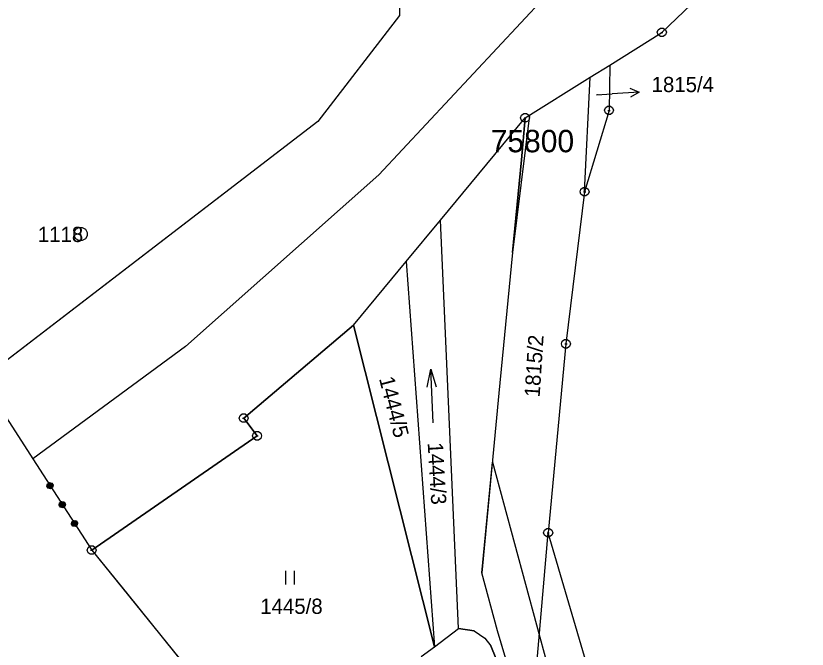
# Model space of a CAD drawing. Extents: x -779618 to -776429, y -1144546 to -1143350.
# Drawn here: x -779325.9 to -779237.8, y -1144354.3 to -1144283.6 of the extents above; entities that cross this region are included whole.
import ezdxf

# ---------------------------------------------------------------- set-up
doc = ezdxf.new("R2010")
doc.units = 0
for name, color, linetype in [('1', 7, 'Continuous'), ('11', 7, 'Continuous'), ('2', 7, 'Continuous'), ('3', 7, 'Continuous'), ('6', 7, 'Continuous'), ('7', 7, 'Continuous'), ('8', 7, 'Continuous')]:
    doc.layers.add(name, color=color, linetype=linetype)

msp = doc.modelspace()

# ---------------------------------------------------------------- linework, layer by layer
at = {"layer": '1'}
for p, q in [((-779253.95, -1144285.5), (-779237.76, -1144269.92)), ((-779283.19, -1144283.63), (-779292.3, -1144295.43)), ((-779259.77, -1144289.14), (-779253.95, -1144285.5)), ((-779261.95, -1144290.5), (-779259.77, -1144289.14)), ((-779259.77, -1144289.14), (-779259.84, -1144294.2)), ((-779269.19, -1144295.03), (-779261.95, -1144290.5)), ((-779262.56, -1144303.28), (-779261.95, -1144290.5)), ((-779259.84, -1144294.2), (-779262.56, -1144303.28)), ((-779292.3, -1144295.43), (-779329.76, -1144324.23)), ((-779278.62, -1144306.44), (-779269.19, -1144295.03)), ((-779269.19, -1144295.03), (-779269.59, -1144299.72)), ((-779269.59, -1144299.72), (-779272.11, -1144325.73)), ((-779262.56, -1144303.28), (-779264.64, -1144320.25)), ((-779282.44, -1144311.07), (-779278.62, -1144306.44)), ((-779276.6, -1144352), (-779278.62, -1144306.44)), ((-779288.3, -1144318.16), (-779282.44, -1144311.07)), ((-779282.44, -1144311.07), (-779279.28, -1144354.03)), ((-779288.3, -1144318.16), (-779300.55, -1144328.53)), ((-779279.28, -1144354.03), (-779288.3, -1144318.16)), ((-779264.64, -1144320.25), (-779266.62, -1144341.31)), ((-779329.76, -1144324.23), (-779324.06, -1144333.07)), ((-779272.11, -1144325.73), (-779274.02, -1144345.79)), ((-779300.55, -1144328.53), (-779299.06, -1144330.51)), ((-779299.06, -1144330.51), (-779317.49, -1144343.25)), ((-779324.06, -1144333.07), (-779317.49, -1144343.25)), ((-779267.93, -1144356.45), (-779266.62, -1144341.31)), ((-779261.4, -1144359.15), (-779266.62, -1144341.31)), ((-779317.49, -1144343.25), (-779313.48, -1144348.21)), ((-779272.28, -1144352.24), (-779274.02, -1144345.79)), ((-779313.48, -1144348.21), (-779297.37, -1144368.14)), ((-779279.28, -1144354.03), (-779276.6, -1144352)), ((-779274.88, -1144352.25), (-779276.6, -1144352)), ((-779274.88, -1144352.25), (-779273.67, -1144353.06)), ((-779273.67, -1144353.06), (-779273.01, -1144353.91)), ((-779268.45, -1144365.11), (-779272.28, -1144352.24)), ((-779272.46, -1144355.3), (-779273.01, -1144353.91)), ((-779280.78, -1144355.1), (-779279.28, -1144354.03))]:
    msp.add_line(p, q, dxfattribs=at)
for points in [[(-779321.792, -1144335.996), (-779321.849, -1144336.258), (-779322.076, -1144336.405), (-779322.338, -1144336.348), (-779322.485, -1144336.122), (-779322.428, -1144335.859), (-779322.202, -1144335.712), (-779321.939, -1144335.769), (-779321.792, -1144335.996), (-779321.821, -1144336.026), (-779321.951, -1144335.824), (-779322.061, -1144335.8), (-779321.844, -1144336.136), (-779321.879, -1144336.23), (-779322.172, -1144335.777), (-779322.239, -1144335.82), (-779321.952, -1144336.265), (-779322.013, -1144336.317), (-779322.301, -1144335.872), (-779322.368, -1144335.915), (-779322.081, -1144336.36), (-779322.175, -1144336.362), (-779322.408, -1144336.001), (-779322.437, -1144336.103), (-779322.285, -1144336.338)], [(-779320.43, -1144338.104), (-779320.487, -1144338.367), (-779320.714, -1144338.513), (-779320.976, -1144338.457), (-779321.123, -1144338.23), (-779321.066, -1144337.967), (-779320.839, -1144337.821), (-779320.577, -1144337.877), (-779320.43, -1144338.104), (-779320.469, -1144338.117), (-779320.6, -1144337.916), (-779320.71, -1144337.892), (-779320.493, -1144338.228), (-779320.517, -1144338.338), (-779320.821, -1144337.868), (-779320.888, -1144337.912), (-779320.584, -1144338.382), (-779320.651, -1144338.425), (-779320.955, -1144337.955), (-779321.022, -1144337.998), (-779320.718, -1144338.469), (-779320.829, -1144338.445), (-779321.046, -1144338.109), (-779321.07, -1144338.22), (-779320.94, -1144338.421)], [(-779319.068, -1144340.212), (-779319.125, -1144340.475), (-779319.351, -1144340.621), (-779319.614, -1144340.565), (-779319.761, -1144340.338), (-779319.704, -1144340.075), (-779319.477, -1144339.929), (-779319.215, -1144339.985), (-779319.068, -1144340.212), (-779319.123, -1144340.2), (-779319.254, -1144339.999), (-779319.353, -1144339.992), (-779319.147, -1144340.311), (-779319.171, -1144340.422), (-779319.453, -1144339.985), (-779319.52, -1144340.028), (-779319.238, -1144340.465), (-779319.305, -1144340.508), (-779319.588, -1144340.072), (-779319.66, -1144340.107), (-779319.378, -1144340.543), (-779319.467, -1144340.553), (-779319.689, -1144340.209), (-779319.729, -1144340.294), (-779319.599, -1144340.496)]]:
    msp.add_lwpolyline(points, dxfattribs=at)
at = {"layer": '11'}
for points in [[(-779393.54, -1144175.59), (-779363.98, -1144153.41), (-779349.51, -1144142.56), (-779304.36, -1144115.54), (-779295.74, -1144129.72), (-779278.85, -1144157.52), (-779271.57, -1144169.5), (-779271.48, -1144169.65), (-779279.8, -1144196.5), (-779281.54, -1144202.11), (-779283.19, -1144283.63), (-779292.3, -1144295.43), (-779329.76, -1144324.23)], [(-779317.49, -1144343.25), (-779299.06, -1144330.51), (-779300.55, -1144328.53), (-779288.3, -1144318.16), (-779279.28, -1144354.03), (-779276.6, -1144352), (-779274.88, -1144352.25), (-779273.67, -1144353.06), (-779273.01, -1144353.91), (-779272.46, -1144355.3)], [(-779317.49, -1144343.25), (-779297.37, -1144368.14), (-779281.3, -1144388.02), (-779277.14, -1144393.17), (-779258.95, -1144412.38)]]:
    msp.add_lwpolyline(points, dxfattribs=at)
for points in [[(-779269.19, -1144295.03), (-779268.71, -1144294.73), (-779270.59, -1144310.06), (-779269.59, -1144299.72)], [(-779274.02, -1144345.79), (-779272.84, -1144333.45), (-779265.46, -1144360.65), (-779256.38, -1144387.71), (-779248.84, -1144402.87), (-779249.94, -1144408.94), (-779252.15, -1144403.93), (-779260.3, -1144384.66), (-779262.26, -1144385.46), (-779264.02, -1144380.83), (-779263.86, -1144380.76), (-779265.81, -1144375.51), (-779264.55, -1144374.32), (-779268.45, -1144365.11), (-779272.28, -1144352.24)]]:
    msp.add_lwpolyline(points, close=True, dxfattribs=at)
at = {"layer": '3'}
for p, q in [((-779279.436, -1144329.057), (-779279.684, -1144323.063)), ((-779295.88, -1144345.57), (-779295.88, -1144347.07)), ((-779294.88, -1144347.07), (-779294.88, -1144345.57))]:
    msp.add_line(p, q, dxfattribs=at)
msp.add_lwpolyline([(-779280.101, -1144325.081), (-779279.684, -1144323.063), (-779279.102, -1144325.04)], dxfattribs=at)
at = {"layer": '6'}
for p, q in [((-779265.64, -1144280.11), (-779285.51, -1144301.4)), ((-779307.04, -1144320.53), (-779285.51, -1144301.4)), ((-779307.04, -1144320.53), (-779324.06, -1144333.07))]:
    msp.add_line(p, q, dxfattribs=at)
at = {"layer": '7'}
for p in [(-779256.487, -1144292.157), (-779261.25, -1144292.48)]:
    msp.add_line(p, (-779259.48, -1144292.36), dxfattribs=at)
msp.add_lwpolyline([(-779257.518, -1144291.726), (-779256.487, -1144292.157), (-779257.451, -1144292.724)], dxfattribs=at)
at = {"layer": '8'}
for p, q in [((-779254.07, -1144285.5), (-779253.83, -1144285.5)), ((-779259.96, -1144294.2), (-779259.72, -1144294.2)), ((-779269.31, -1144295.03), (-779269.07, -1144295.03)), ((-779262.68, -1144303.28), (-779262.44, -1144303.28)), ((-779318.78, -1144307.99), (-779318.68, -1144307.99)), ((-779264.76, -1144320.25), (-779264.52, -1144320.25)), ((-779300.67, -1144328.53), (-779300.43, -1144328.53)), ((-779299.18, -1144330.51), (-779298.94, -1144330.51)), ((-779266.74, -1144341.31), (-779266.5, -1144341.31)), ((-779317.61, -1144343.25), (-779317.37, -1144343.25))]:
    msp.add_line(p, q, dxfattribs=at)
for points in [[(-779253.8, -1144285.02), (-779253.55, -1144285.2), (-779253.45, -1144285.49), (-779253.55, -1144285.78), (-779253.8, -1144285.96), (-779254.11, -1144285.96), (-779254.36, -1144285.78), (-779254.46, -1144285.49), (-779254.36, -1144285.2), (-779254.11, -1144285.02)], [(-779259.69, -1144293.72), (-779259.44, -1144293.9), (-779259.34, -1144294.19), (-779259.44, -1144294.48), (-779259.69, -1144294.66), (-779260, -1144294.66), (-779260.25, -1144294.48), (-779260.35, -1144294.19), (-779260.25, -1144293.9), (-779260, -1144293.72)], [(-779269.04, -1144294.55), (-779268.79, -1144294.73), (-779268.69, -1144295.02), (-779268.79, -1144295.31), (-779269.04, -1144295.49), (-779269.35, -1144295.49), (-779269.6, -1144295.31), (-779269.7, -1144295.02), (-779269.6, -1144294.73), (-779269.35, -1144294.55)], [(-779262.41, -1144302.8), (-779262.16, -1144302.98), (-779262.06, -1144303.27), (-779262.16, -1144303.56), (-779262.41, -1144303.74), (-779262.72, -1144303.74), (-779262.97, -1144303.56), (-779263.07, -1144303.27), (-779262.97, -1144302.98), (-779262.72, -1144302.8)], [(-779318.54, -1144307.27), (-779318.2, -1144307.46), (-779318.01, -1144307.8), (-779318.01, -1144308.19), (-779318.2, -1144308.53), (-779318.54, -1144308.72), (-779318.93, -1144308.72), (-779319.27, -1144308.53), (-779319.46, -1144308.19), (-779319.46, -1144307.8), (-779319.27, -1144307.46), (-779318.93, -1144307.27)], [(-779264.49, -1144319.77), (-779264.24, -1144319.95), (-779264.14, -1144320.24), (-779264.24, -1144320.53), (-779264.49, -1144320.71), (-779264.8, -1144320.71), (-779265.05, -1144320.53), (-779265.15, -1144320.24), (-779265.05, -1144319.95), (-779264.8, -1144319.77)], [(-779300.4, -1144328.05), (-779300.15, -1144328.23), (-779300.05, -1144328.52), (-779300.15, -1144328.81), (-779300.4, -1144328.99), (-779300.71, -1144328.99), (-779300.96, -1144328.81), (-779301.06, -1144328.52), (-779300.96, -1144328.23), (-779300.71, -1144328.05)], [(-779298.91, -1144330.03), (-779298.66, -1144330.21), (-779298.56, -1144330.5), (-779298.66, -1144330.79), (-779298.91, -1144330.97), (-779299.22, -1144330.97), (-779299.47, -1144330.79), (-779299.57, -1144330.5), (-779299.47, -1144330.21), (-779299.22, -1144330.03)], [(-779266.47, -1144340.83), (-779266.22, -1144341.01), (-779266.12, -1144341.3), (-779266.22, -1144341.59), (-779266.47, -1144341.77), (-779266.78, -1144341.77), (-779267.03, -1144341.59), (-779267.13, -1144341.3), (-779267.03, -1144341.01), (-779266.78, -1144340.83)], [(-779317.34, -1144342.77), (-779317.09, -1144342.95), (-779316.99, -1144343.24), (-779317.09, -1144343.53), (-779317.34, -1144343.71), (-779317.65, -1144343.71), (-779317.9, -1144343.53), (-779318, -1144343.24), (-779317.9, -1144342.95), (-779317.65, -1144342.77)]]:
    msp.add_lwpolyline(points, close=True, dxfattribs=at)

# ---------------------------------------------------------------- texts
at = {"layer": '11'}
msp.add_text('75800', height=2.5, dxfattribs=at).set_placement((-779273.029, -1144298.87))
at = {"layer": '2'}
for s, height, p in [('1815/4', 0.1, (-779261.227, -1144292.48)), ('1445/8', 1.7, (-779298.707, -1144350.36))]:
    msp.add_text(s, height=height, dxfattribs=at).set_placement(p)
for s, rotation, p in [('1815/2', 86.28744, (-779267.575, -1144326.228)), ('1444/5', 284.41625, (-779285.482, -1144324.11)), ('1444/3', 273.41546, (-779280.057, -1144331.282))]:
    msp.add_text(s, height=1.7, rotation=rotation, dxfattribs=at).set_placement(p)
at = {"layer": '7'}
msp.add_text('1815/4', height=1.7, dxfattribs=at).set_placement((-779255.097, -1144292.16))
at = {"layer": '8'}
msp.add_text('1118', height=1.7, dxfattribs=at).set_placement((-779323.497, -1144308.88))

doc.saveas('drawing.dxf')
